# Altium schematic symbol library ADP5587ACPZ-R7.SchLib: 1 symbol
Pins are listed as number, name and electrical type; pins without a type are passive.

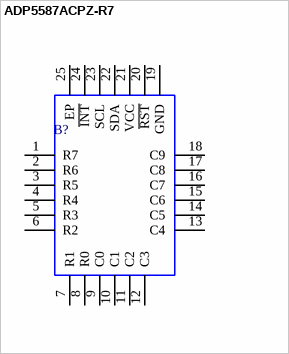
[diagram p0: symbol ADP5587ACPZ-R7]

## ADP5587ACPZ-R7
designator B?
Analog Devices ADP5587ACPZ-R7, 18-channel 18bit I/O Expander 400kHz, I2C, 24-Pin LFCSP WQ; Geometry.Height: 0.8mm
footprint QFN50P400X400X80-25N-D
pins: 1 R7, 2 R6, 3 R5, 4 R4, 5 R3, 6 R2, 7 R1, 8 R0, 9 C0, 10 C1, 11 C2, 12 C3, 13 C4, 14 C5, 15 C6, 16 C7, 17 C8, 18 C9, 19 GND, 20 ~{RST}, 21 VCC, 22 SDA, 23 SCL, 24 ~{INT}, 25 EP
